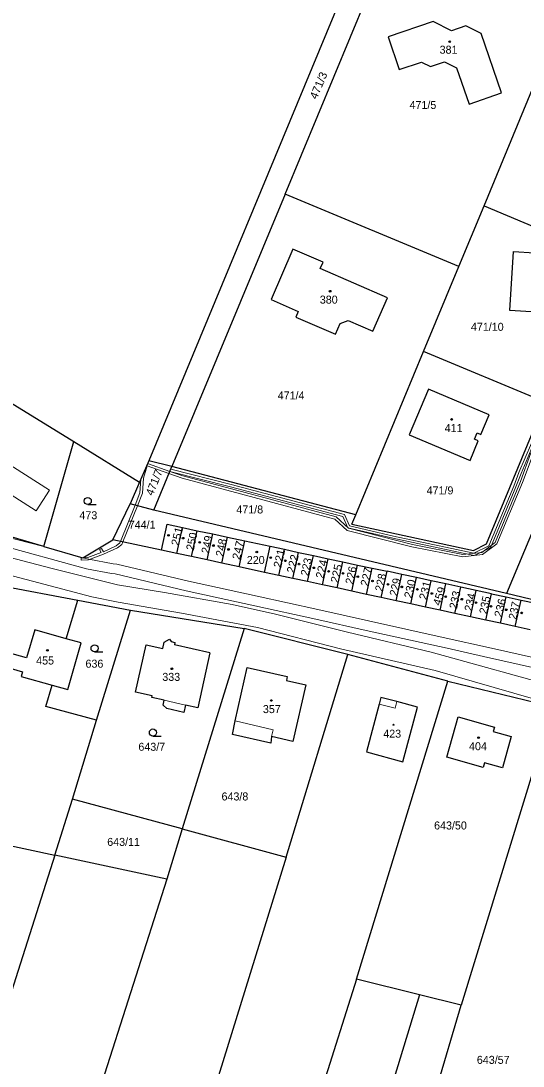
# Model space of a CAD drawing. Extents: x -701211 to -698780, y -1014269 to -1012378.
# Drawn here: x -700007.4 to -699900.8, y -1013587.7 to -1013365.7 of the extents above; entities that cross this region are included whole.
import ezdxf
from ezdxf.enums import TextEntityAlignment as Align

# ---------------------------------------------------------------- set-up
doc = ezdxf.new("R2010")
doc.units = 0
doc.header["$LTSCALE"] = 0.68
for name, color, linetype, lineweight in [('1', 7, 'Continuous', 25), ('13', 7, 'Continuous', 13), ('3', 7, 'Continuous', 25), ('4', 7, 'Continuous', 13), ('5', 7, 'Continuous', 25)]:
    doc.layers.add(name, color=color, linetype=linetype, lineweight=lineweight)
doc.layers.add('2', color=7, linetype='Continuous')

msp = doc.modelspace()

# ---------------------------------------------------------------- linework, layer by layer
at = {"layer": '1'}
for p, q in [((-699951.32, -1013402.53), (-699926.55, -1013342.94)), ((-699934.3, -1013348.53), (-699980.25, -1013459.13)), ((-699919.88, -1013365.87), (-699929.45, -1013369.13)), ((-699915.99, -1013367.87), (-699919.88, -1013365.87)), ((-699912.89, -1013366.77), (-699915.99, -1013367.87)), ((-699909.63, -1013368.45), (-699912.89, -1013366.77)), ((-699909.05, -1013405.04), (-699893.69, -1013367.83)), ((-699929.45, -1013369.13), (-699927.09, -1013376.09)), ((-699905.33, -1013381.05), (-699909.63, -1013368.45)), ((-699920.4, -1013375.45), (-699917.42, -1013374.47)), ((-699917.42, -1013374.47), (-699914.87, -1013375.71)), ((-699927.09, -1013376.09), (-699922.37, -1013374.53)), ((-699922.37, -1013374.53), (-699920.4, -1013375.45)), ((-699914.87, -1013375.71), (-699912.24, -1013383.4)), ((-699912.24, -1013383.4), (-699905.33, -1013381.05)), ((-699951.32, -1013402.53), (-699975.36, -1013460.38)), ((-699914.39, -1013417.88), (-699951.32, -1013402.53)), ((-699914.39, -1013417.88), (-699909.05, -1013405.04)), ((-699909.05, -1013405.04), (-699890.85, -1013412.64)), ((-699949.64, -1013414.18), (-699954.3, -1013424.93)), ((-699943.25, -1013416.95), (-699949.64, -1013414.18)), ((-699903.54, -1013427.24), (-699902.78, -1013414.7)), ((-699902.78, -1013414.7), (-699898.32, -1013414.97)), ((-699943.85, -1013418.33), (-699943.25, -1013416.95)), ((-699929.59, -1013424.52), (-699943.85, -1013418.33)), ((-699921.89, -1013435.93), (-699914.39, -1013417.88)), ((-699954.3, -1013424.93), (-699948.52, -1013427.44)), ((-699932.67, -1013431.64), (-699929.59, -1013424.52)), ((-699948.52, -1013427.44), (-699949.03, -1013428.62)), ((-699899.06, -1013427.52), (-699903.54, -1013427.24)), ((-699949.03, -1013428.62), (-699940.58, -1013432.28)), ((-699939.59, -1013429.99), (-699937.95, -1013429.35)), ((-699937.95, -1013429.35), (-699932.67, -1013431.64)), ((-699940.58, -1013432.28), (-699939.59, -1013429.99)), ((-700026.39, -1013436.44), (-699996.22, -1013455.06)), ((-699936.32, -1013470.64), (-699921.89, -1013435.93)), ((-699896.06, -1013446.72), (-699921.89, -1013435.93)), ((-699920.88, -1013443.93), (-699924.96, -1013453.63)), ((-699907.97, -1013449.38), (-699920.88, -1013443.93)), ((-699908.56, -1013476.78), (-699896.06, -1013446.72)), ((-699909.7, -1013453.55), (-699907.97, -1013449.38)), ((-699924.96, -1013453.63), (-699912.02, -1013459.07)), ((-699911.1, -1013454.57), (-699910.52, -1013453.2)), ((-699910.52, -1013453.2), (-699909.7, -1013453.55)), ((-700002.55, -1013477.36), (-699996.22, -1013455.06)), ((-699996.22, -1013455.06), (-699982.22, -1013463.69)), ((-699912.02, -1013459.07), (-699910.28, -1013454.92)), ((-699910.28, -1013454.92), (-699911.1, -1013454.57)), ((-699892.04, -1013457.91), (-699904.27, -1013487.36)), ((-699980.25, -1013459.13), (-699982.22, -1013463.69)), ((-699975.36, -1013460.38), (-699980.25, -1013459.13)), ((-699979.2, -1013469.62), (-699975.36, -1013460.38)), ((-699936.32, -1013470.64), (-699975.36, -1013460.38)), ((-699982.22, -1013463.69), (-699984.21, -1013468.3)), ((-699987.89, -1013475.93), (-699984.21, -1013468.3)), ((-699979.2, -1013469.62), (-699984.21, -1013468.3)), ((-699904.27, -1013487.36), (-699979.2, -1013469.62)), ((-699937.15, -1013472.63), (-699936.32, -1013470.64)), ((-700002.55, -1013477.36), (-700016.78, -1013473.19)), ((-699977.58, -1013478.12), (-699976.38, -1013472.62)), ((-699976.38, -1013472.62), (-699973.1, -1013473.32)), ((-699974.3, -1013478.83), (-699973.1, -1013473.32)), ((-699973.1, -1013473.32), (-699969.97, -1013473.99)), ((-699971.18, -1013479.5), (-699969.97, -1013473.99)), ((-699969.97, -1013473.99), (-699966.69, -1013474.69)), ((-699937.15, -1013472.63), (-699911.29, -1013478.21)), ((-699994.3, -1013479.75), (-699987.89, -1013475.93)), ((-699977.58, -1013478.12), (-699987.89, -1013475.93)), ((-699967.9, -1013480.21), (-699966.69, -1013474.69)), ((-699966.69, -1013474.69), (-699963.56, -1013475.36)), ((-699964.77, -1013480.89), (-699963.56, -1013475.36)), ((-699963.56, -1013475.36), (-699959.86, -1013476.15)), ((-699961.07, -1013481.68), (-699959.86, -1013476.15)), ((-699959.86, -1013476.15), (-699954.46, -1013477.31)), ((-700002.55, -1013477.36), (-699994.3, -1013479.75)), ((-699974.3, -1013478.83), (-699977.58, -1013478.12)), ((-699955.68, -1013482.84), (-699954.46, -1013477.31)), ((-699954.46, -1013477.31), (-699951.45, -1013477.95)), ((-699952.67, -1013483.49), (-699951.45, -1013477.95)), ((-699951.45, -1013477.95), (-699948.44, -1013478.6)), ((-699949.66, -1013484.14), (-699948.44, -1013478.6)), ((-699948.44, -1013478.6), (-699945.31, -1013479.27)), ((-699911.29, -1013478.21), (-699908.56, -1013476.78)), ((-699971.18, -1013479.5), (-699974.3, -1013478.83)), ((-699967.9, -1013480.21), (-699971.18, -1013479.5)), ((-699964.77, -1013480.89), (-699967.9, -1013480.21)), ((-699961.07, -1013481.68), (-699964.77, -1013480.89)), ((-699946.53, -1013484.81), (-699945.31, -1013479.27)), ((-699945.31, -1013479.27), (-699942.18, -1013479.94)), ((-699943.4, -1013485.48), (-699942.18, -1013479.94)), ((-699942.18, -1013479.94), (-699939.05, -1013480.61)), ((-699940.27, -1013486.16), (-699939.05, -1013480.61)), ((-699939.05, -1013480.61), (-699935.92, -1013481.28)), ((-699955.68, -1013482.84), (-699961.07, -1013481.68)), ((-699952.67, -1013483.49), (-699955.68, -1013482.84)), ((-699937.14, -1013486.84), (-699935.92, -1013481.28)), ((-699935.92, -1013481.28), (-699932.79, -1013481.95)), ((-699934.01, -1013487.51), (-699932.79, -1013481.95)), ((-699932.79, -1013481.95), (-699929.66, -1013482.62)), ((-699930.88, -1013488.19), (-699929.66, -1013482.62)), ((-699926.53, -1013483.29), (-699929.66, -1013482.62)), ((-699949.66, -1013484.14), (-699952.67, -1013483.49)), ((-699946.53, -1013484.81), (-699949.66, -1013484.14)), ((-699943.4, -1013485.48), (-699946.53, -1013484.81)), ((-699927.75, -1013488.87), (-699926.53, -1013483.29)), ((-699923.4, -1013483.96), (-699926.53, -1013483.29)), ((-699924.62, -1013489.54), (-699923.4, -1013483.96)), ((-699920.27, -1013484.63), (-699923.4, -1013483.96)), ((-699921.49, -1013490.22), (-699920.27, -1013484.63)), ((-699917.14, -1013485.3), (-699920.27, -1013484.63)), ((-699918.36, -1013490.89), (-699917.14, -1013485.3)), ((-699914.01, -1013485.97), (-699917.14, -1013485.3)), ((-700011.93, -1013485.64), (-699995.35, -1013488.75)), ((-699940.27, -1013486.16), (-699943.4, -1013485.48)), ((-699930.88, -1013488.19), (-699934.01, -1013487.51)), ((-699915.23, -1013491.56), (-699914.01, -1013485.97)), ((-699910.73, -1013486.68), (-699914.01, -1013485.97)), ((-699911.95, -1013492.27), (-699910.73, -1013486.68)), ((-699907.45, -1013487.38), (-699910.73, -1013486.68)), ((-699907.45, -1013487.38), (-699904.32, -1013488.06)), ((-699872.52, -1013494.88), (-699904.27, -1013487.36)), ((-699997.82, -1013496.92), (-699995.35, -1013488.75)), ((-699995.35, -1013488.75), (-699984.16, -1013490.84)), ((-699927.75, -1013488.87), (-699930.88, -1013488.19)), ((-699924.62, -1013489.54), (-699927.75, -1013488.87)), ((-699921.49, -1013490.22), (-699924.62, -1013489.54)), ((-699905.54, -1013493.65), (-699904.32, -1013488.06)), ((-699904.32, -1013488.06), (-699901.19, -1013488.73)), ((-699902.41, -1013494.33), (-699901.19, -1013488.73)), ((-699901.19, -1013488.73), (-699898.06, -1013489.4)), ((-699991.36, -1013514.25), (-699984.16, -1013490.84)), ((-699984.16, -1013490.84), (-699959.98, -1013494.73)), ((-699918.36, -1013490.89), (-699921.49, -1013490.22)), ((-699915.23, -1013491.56), (-699918.36, -1013490.89)), ((-699911.95, -1013492.27), (-699915.23, -1013491.56)), ((-699908.67, -1013492.98), (-699911.95, -1013492.27)), ((-699902.41, -1013494.33), (-699905.54, -1013493.65)), ((-699899.28, -1013495.01), (-699902.41, -1013494.33)), ((-700004.51, -1013495.01), (-700006.25, -1013501.02)), ((-699997.82, -1013496.92), (-700004.51, -1013495.01)), ((-699959.98, -1013494.73), (-699973.17, -1013537.33)), ((-699937.98, -1013500.29), (-699959.98, -1013494.73)), ((-699994.61, -1013497.83), (-699997.82, -1013496.92)), ((-699997.44, -1013507.72), (-699994.61, -1013497.83)), ((-699983.07, -1013508.25), (-699980.82, -1013498.2)), ((-699980.82, -1013498.2), (-699977.31, -1013498.99)), ((-699977.31, -1013498.99), (-699977.01, -1013497.67)), ((-699977.01, -1013497.67), (-699975.84, -1013497.03)), ((-699975.84, -1013497.03), (-699975.49, -1013497.55)), ((-699975.49, -1013497.55), (-699974.71, -1013497.73)), ((-699974.71, -1013497.73), (-699974.82, -1013498.26)), ((-699967.27, -1013499.96), (-699974.82, -1013498.26)), ((-700006.25, -1013501.02), (-700011.9, -1013499.4)), ((-699967.27, -1013499.96), (-699969.85, -1013511.6)), ((-699951.12, -1013543.34), (-699937.98, -1013500.29)), ((-699916.77, -1013505.91), (-699937.98, -1013500.29)), ((-700012.73, -1013502.3), (-700007.08, -1013503.93)), ((-699961.92, -1013514.4), (-699959.35, -1013503.02)), ((-699959.35, -1013503.02), (-699950.89, -1013504.96)), ((-700007.08, -1013503.93), (-700007.36, -1013504.92)), ((-700007.36, -1013504.92), (-700000.79, -1013506.78)), ((-699950.89, -1013504.96), (-699951.05, -1013505.81)), ((-700002.17, -1013511.33), (-700000.79, -1013506.78)), ((-700000.79, -1013506.78), (-699997.44, -1013507.72)), ((-699951.05, -1013505.81), (-699946.93, -1013506.74)), ((-699946.93, -1013506.74), (-699949.68, -1013518.75)), ((-699936.17, -1013569.22), (-699916.77, -1013505.91)), ((-699916.77, -1013505.91), (-699894.47, -1013511.36)), ((-699979.57, -1013509.03), (-699983.07, -1013508.25)), ((-699979.65, -1013509.39), (-699979.57, -1013509.03)), ((-699977.01, -1013509.99), (-699979.65, -1013509.39)), ((-699930.95, -1013509.39), (-699931.33, -1013510.81)), ((-699927.55, -1013510.28), (-699930.95, -1013509.39)), ((-699991.36, -1013514.25), (-700002.17, -1013511.33)), ((-699977.24, -1013511.06), (-699977.01, -1013509.99)), ((-699976.45, -1013511.75), (-699977.24, -1013511.06)), ((-699972.82, -1013512.57), (-699976.45, -1013511.75)), ((-699972.47, -1013511.02), (-699972.82, -1013512.57)), ((-699969.85, -1013511.6), (-699972.47, -1013511.02)), ((-699931.33, -1013510.81), (-699934.03, -1013520.97)), ((-699923.18, -1013511.45), (-699927.55, -1013510.28)), ((-699926.27, -1013523.04), (-699923.18, -1013511.45)), ((-699894.47, -1013511.36), (-699913.94, -1013574.75)), ((-699996.51, -1013530.97), (-699991.36, -1013514.25)), ((-699916.96, -1013522.07), (-699914.54, -1013513.49)), ((-699914.54, -1013513.49), (-699906.84, -1013515.68)), ((-699962.47, -1013517.27), (-699961.92, -1013514.4)), ((-699906.84, -1013515.68), (-699907.12, -1013516.64)), ((-699954.37, -1013519.13), (-699962.47, -1013517.27)), ((-699954.2, -1013517.71), (-699954.37, -1013519.13)), ((-699949.68, -1013518.75), (-699954.2, -1013517.71)), ((-699907.12, -1013516.64), (-699903.27, -1013517.71)), ((-699903.27, -1013517.71), (-699905.15, -1013524.33)), ((-699934.03, -1013520.97), (-699926.27, -1013523.04)), ((-699909.26, -1013524.25), (-699916.96, -1013522.07)), ((-699908.97, -1013523.28), (-699909.26, -1013524.25)), ((-699905.15, -1013524.33), (-699908.97, -1013523.28)), ((-700000.2, -1013542.89), (-699996.51, -1013530.97)), ((-699973.17, -1013537.33), (-699996.51, -1013530.97)), ((-700026.49, -1013537.22), (-700000.2, -1013542.89)), ((-699973.17, -1013537.33), (-699976.45, -1013548.01)), ((-699973.17, -1013537.33), (-699951.12, -1013543.34)), ((-700000.2, -1013542.89), (-700050.45, -1013699.97)), ((-699976.45, -1013548.01), (-700000.2, -1013542.89)), ((-699951.12, -1013543.34), (-700001.73, -1013706.62)), ((-699976.45, -1013548.01), (-700017.87, -1013677.63)), ((-699936.17, -1013569.22), (-699952.34, -1013620.52)), ((-699922.75, -1013572.56), (-699936.17, -1013569.22)), ((-699922.75, -1013572.56), (-699938.67, -1013624.48)), ((-699913.94, -1013574.75), (-699922.75, -1013572.56)), ((-699919.84, -1013594.85), (-699913.94, -1013574.75))]:
    msp.add_line(p, q, dxfattribs=at)
for points in [[(-699934.01, -1013487.51), (-699937.14, -1013486.84), (-699940.27, -1013486.16)], [(-699905.54, -1013493.65), (-699908.67, -1013492.98), (-699907.45, -1013487.38)]]:
    msp.add_lwpolyline(points, dxfattribs=at)
at = {"layer": '13'}
for points in [[(-699899, -1013455.41), (-699901.64, -1013461.65), (-699902.75, -1013464.51), (-699908.03, -1013477.24), (-699911.19, -1013478.77), (-699928.32, -1013475.13), (-699937.62, -1013472.97), (-699938.67, -1013470.55), (-699962.76, -1013464.17), (-699975.58, -1013460.92), (-699975.78, -1013461.39), (-699962.88, -1013464.65), (-699939.03, -1013470.97), (-699937.98, -1013473.41), (-699928.42, -1013475.61), (-699911.13, -1013479.29), (-699907.65, -1013477.6), (-699902.29, -1013464.69), (-699901.18, -1013461.83), (-699898.67, -1013455.91)], [(-699899.1, -1013457.48), (-699901.31, -1013463.56), (-699906.71, -1013476.48), (-699909.54, -1013478.59), (-699913.54, -1013479.03), (-699924.28, -1013476.91), (-699937.86, -1013473.47), (-699940.49, -1013471.07), (-699973.01, -1013462.36), (-699975.78, -1013461.4), (-699975.98, -1013461.86), (-699973.15, -1013462.84), (-699940.73, -1013471.53), (-699938.1, -1013473.93), (-699924.39, -1013477.39), (-699913.56, -1013479.53), (-699909.35, -1013479.07), (-699906.31, -1013476.8), (-699900.85, -1013463.74), (-699898.65, -1013457.72)], [(-700079.92, -1013464.99), (-699992.36, -1013488.02), (-699986.75, -1013489.19), (-699973.34, -1013491.5), (-699957.16, -1013494.57), (-699939.54, -1013499.05), (-699919.44, -1013503.71), (-699898.51, -1013509.71), (-699886.6, -1013512.43), (-699874.62, -1013514.42), (-699862.75, -1013516.78), (-699859.41, -1013517.38), (-699855.41, -1013517.44), (-699834.64, -1013518.82), (-699813.16, -1013519.22), (-699809.23, -1013520.19), (-699776.25, -1013520.12), (-699772.21, -1013519.8), (-699747.11, -1013516.91)], [(-699747.47, -1013513.83), (-699772.47, -1013516.71), (-699781.76, -1013516.59), (-699791.73, -1013516.61), (-699806.17, -1013516.71), (-699814.27, -1013516.52), (-699820.54, -1013516.46), (-699836.64, -1013516.04), (-699849.43, -1013515.5), (-699873.2, -1013511), (-699892.18, -1013507.57), (-699920.26, -1013499.8), (-699938.09, -1013495.57), (-699953.33, -1013491.72), (-699962.58, -1013489.69), (-699976.91, -1013487.15), (-699986.95, -1013485.46), (-700001.06, -1013481.97), (-700024.67, -1013475.8)], [(-699994.3, -1013479.75), (-700002.55, -1013477.36), (-700011.13, -1013475.12)], [(-700012.63, -1013476.85), (-699993.48, -1013482.08), (-699988.16, -1013483.07), (-699987.39, -1013483.16), (-699972.3, -1013486.74), (-699957.72, -1013489.94), (-699944.78, -1013492.78), (-699934.06, -1013495.18), (-699916.9, -1013498.97), (-699909.19, -1013500.69), (-699878.22, -1013507.61), (-699872.13, -1013508.98), (-699869.2, -1013509.93), (-699862.6, -1013512.07), (-699856.82, -1013512.65), (-699852.31, -1013513.11), (-699840.03, -1013514.33), (-699823.11, -1013514.93), (-699802.22, -1013515.68), (-699777.04, -1013516.58), (-699775.1, -1013516.71), (-699774.97, -1013514.65), (-699775.96, -1013514.58), (-699775.95, -1013514.28)], [(-699877.77, -1013505.6), (-699908.74, -1013498.67), (-699916.46, -1013496.96), (-699933.62, -1013493.16), (-699944.33, -1013490.76), (-699957.28, -1013487.92), (-699971.84, -1013484.73), (-699987.04, -1013481.12), (-699987.86, -1013481.03), (-699993.02, -1013480.06), (-699994.3, -1013479.75)]]:
    msp.add_lwpolyline(points, dxfattribs=at)
for points in [[(-699981.64, -1013466.04), (-699981.42, -1013462.82), (-699980.62, -1013460.25), (-699975.98, -1013461.86), (-699975.78, -1013461.4), (-699980.52, -1013459.76), (-699981.94, -1013463.05), (-699982.14, -1013465.92), (-699983.2, -1013468.57), (-699982.7, -1013468.7)], [(-699986.94, -1013477.64), (-699985.99, -1013476.9), (-699985.78, -1013476.38), (-699982.7, -1013468.7), (-699983.2, -1013468.57), (-699986.28, -1013476.27), (-699986.41, -1013476.59), (-699987.2, -1013477.21), (-699989.91, -1013478.46), (-699990.3, -1013477.75), (-699990.74, -1013477.99), (-699990.38, -1013478.65), (-699993.19, -1013479.71), (-699994.3, -1013479.75), (-699994.65, -1013479.76), (-699994.63, -1013480.26), (-699993.09, -1013480.21), (-699989.92, -1013479.01)]]:
    msp.add_lwpolyline(points, close=True, dxfattribs=at)
at = {"layer": '3'}
for p, q in [((-699993.233, -1013468.44), (-699991.483, -1013468.44)), ((-699991.793, -1013499.72), (-699990.043, -1013499.72)), ((-699979.403, -1013517.6), (-699977.653, -1013517.6))]:
    msp.add_line(p, q, dxfattribs=at)
for centre in [(-699993.2329, -1013467.6898), (-699991.7929, -1013498.9698), (-699979.4029, -1013516.8498)]:
    msp.add_circle(centre, 0.75, dxfattribs=at)
at = {"layer": '4'}
for p, q in [((-700004.17, -1013469.79), (-700023.84, -1013457.2)), ((-700004.17, -1013469.79), (-700001.37, -1013465.42)), ((-699972.47, -1013511.02), (-699977.01, -1013509.99)), ((-699931.33, -1013510.81), (-699927.93, -1013511.71)), ((-699927.93, -1013511.71), (-699927.55, -1013510.28)), ((-699953.87, -1013516.25), (-699961.92, -1013514.4)), ((-699954.2, -1013517.71), (-699953.87, -1013516.25))]:
    msp.add_line(p, q, dxfattribs=at)
msp.add_lwpolyline([(-700001.37, -1013465.42), (-700021.04, -1013452.83), (-700020.18, -1013451.49)], dxfattribs=at)
at = {"layer": '5'}
for centre, radius in [((-699916.3468, -1013370.1692), 0.175), ((-699941.7568, -1013423.1392), 0.175), ((-699915.9468, -1013450.3692), 0.175), ((-699976.0868, -1013474.9792), 0.175), ((-699972.9868, -1013475.5792), 0.175), ((-699969.4568, -1013476.4692), 0.175), ((-699966.5368, -1013477.1392), 0.175), ((-699963.3268, -1013477.9792), 0.175), ((-699957.3368, -1013478.5192), 0.175), ((-699954.3668, -1013479.7192), 0.175), ((-699951.2768, -1013480.3892), 0.175), ((-699948.3468, -1013481.0892), 0.175), ((-699945.2168, -1013481.8792), 0.175), ((-699942.0768, -1013482.6292), 0.175), ((-699938.9968, -1013483.0492), 0.175), ((-699935.8668, -1013483.7492), 0.175), ((-699932.7468, -1013484.6692), 0.175), ((-699929.4468, -1013485.3992), 0.175), ((-699926.5168, -1013485.9292), 0.175), ((-699923.2168, -1013486.4492), 0.175), ((-699920.1368, -1013487.3292), 0.175), ((-699917.1968, -1013488.0092), 0.175), ((-699913.7768, -1013488.5492), 0.175), ((-699910.7568, -1013489.2692), 0.175), ((-699907.5668, -1013490.0492), 0.175), ((-699904.3468, -1013490.7892), 0.175), ((-699901.0468, -1013491.4492), 0.175), ((-700001.7968, -1013499.3992), 0.175), ((-699975.3668, -1013503.3192), 0.175), ((-699954.2368, -1013510.0492), 0.175), ((-699928.2846, -1013515.1994), 0.1172), ((-699910.2168, -1013517.9392), 0.175)]:
    msp.add_circle(centre, radius, dxfattribs=at)

# ---------------------------------------------------------------- texts
at = {"layer": '2'}
for s, p in [('381', (-699918.49, -1013372.715)), ('471/5', (-699924.88, -1013384.445)), ('380', (-699943.94, -1013425.775)), ('471/10', (-699911.84, -1013431.545)), ('471/4', (-699952.89, -1013446.125)), ('411', (-699917.42, -1013453.045)), ('471/9', (-699921.25, -1013466.285)), ('473', (-699995.01, -1013471.565)), ('471/8', (-699961.67, -1013470.335)), ('744/1', (-699984.52, -1013473.565)), ('220', (-699959.45, -1013481.065)), ('636', (-699993.72, -1013503.085)), ('333', (-699977.4, -1013505.885)), ('357', (-699956.03, -1013512.725)), ('423', (-699930.46, -1013517.945)), ('643/7', (-699982.48, -1013520.725)), ('404', (-699912.24, -1013520.605)), ('643/8', (-699964.82, -1013531.275)), ('643/50', (-699919.66, -1013537.435)), ('643/11', (-699989.1, -1013540.925))]:
    msp.add_text(s, height=1.7, dxfattribs=at).set_placement(p)
at = {"layer": '2', "width": 1.05}
for s, rotation, p in [('471/3', 67, (-699944.608, -1013382.526)), ('251', 76, (-699973.917, -1013477.322)), ('247', 77, (-699960.935, -1013480.265)), ('221', 77, (-699952.175, -1013482.015)), ('222', 76, (-699949.367, -1013483.162)), ('224', 77, (-699943.195, -1013484.255)), ('225', 77, (-699940.035, -1013485.215)), ('227', 77, (-699933.695, -1013485.895)), ('230', 77, (-699924.425, -1013488.455)), ('231', 76, (-699921.257, -1013488.802)), ('236', 76, (-699905.287, -1013492.512))]:
    msp.add_text(s, height=1.7, rotation=rotation, dxfattribs=at).set_placement(p)
at = {"layer": '2'}
for s, rotation, p in [('471/7', 68, (-699979.425, -1013466.699)), ('250', 78, (-699970.724, -1013478.298)), ('249', 78, (-699967.494, -1013478.958)), ('248', 79, (-699964.432, -1013479.601)), ('223', 78, (-699946.384, -1013483.698)), ('226', 78, (-699936.894, -1013485.488)), ('228', 78, (-699930.594, -1013487.008)), ('229', 78, (-699927.504, -1013487.978)), ('233', 78, (-699914.814, -1013490.698)), ('234', 78, (-699911.604, -1013491.208)), ('235', 78, (-699908.464, -1013491.788)), ('237', 78, (-699902.224, -1013492.978))]:
    msp.add_text(s, height=1.7, rotation=rotation, dxfattribs=at).set_placement(p)
at = {"layer": '2', "width": 1.05}
msp.add_text('459', height=1.7, rotation=72, dxfattribs=at).set_placement((-699917.7421, -1013488.1467), align=Align.CENTER)
at = {"layer": '2'}
for s, p in [('455', (-700002.299, -1013502.405)), ('643/57', (-699907.1, -1013587.205))]:
    msp.add_text(s, height=1.7, dxfattribs=at).set_placement(p, align=Align.CENTER)

doc.saveas('drawing.dxf')
